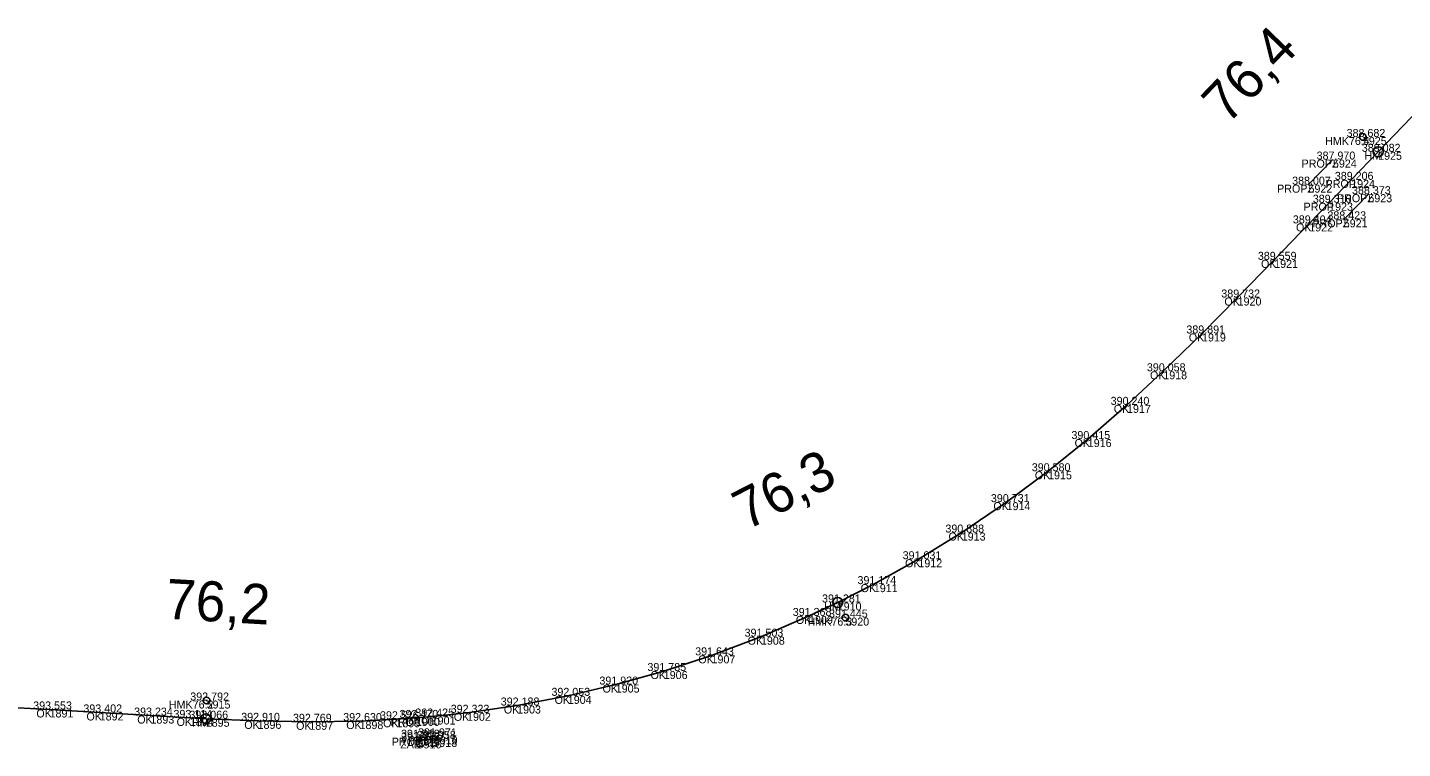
# Model space of a CAD drawing. Extents: x -621782 to -610392, y -1141853 to -1122321.
# Drawn here: x -617837.9 to -617631.7, y -1130433.5 to -1130325.4 of the extents above; entities that cross this region are included whole.
import ezdxf

# ---------------------------------------------------------------- set-up
doc = ezdxf.new("R2010")
doc.units = 0
for name, color, linetype in [('Vrstva 1', 7, 'Continuous'), ('Vrstva 17', 7, 'Continuous'), ('Vrstva 19', 7, 'Continuous'), ('Vrstva 60', 7, 'Continuous'), ('Vrstva 61', 7, 'Continuous'), ('Vrstva 62', 7, 'Continuous'), ('Vrstva 7', 7, 'Continuous')]:
    doc.layers.add(name, color=color, linetype=linetype)

msp = doc.modelspace()

# ---------------------------------------------------------------- linework, layer by layer
at = {"layer": 'Vrstva 1'}
msp.add_lwpolyline([(-617842.32, -1130427.24), (-617834.59, -1130427.64), (-617827.07, -1130428.09), (-617819.46, -1130428.56), (-617813.56, -1130428.91), (-617811.17, -1130429.03), (-617803.4, -1130429.35), (-617795.64, -1130429.49), (-617788.11, -1130429.38), (-617782.58, -1130429.11), (-617779.66, -1130428.91), (-617777.29, -1130428.7), (-617771.99, -1130428.14), (-617764.48, -1130427.05), (-617756.88, -1130425.6), (-617749.69, -1130423.91), (-617742.49, -1130421.88), (-617735.33, -1130419.53), (-617727.92, -1130416.73), (-617720.7, -1130413.62), (-617716.41, -1130411.6), (-617710.99, -1130408.85), (-617704.31, -1130405.12), (-617697.81, -1130401.12), (-617691.08, -1130396.56), (-617684.86, -1130391.93), (-617678.91, -1130387.1), (-617673.03, -1130381.97), (-617667.59, -1130376.94), (-617661.78, -1130371.27), (-617656.44, -1130365.88), (-617650.96, -1130360.23), (-617645.71, -1130354.77), (-617642.72, -1130351.67), (-617639.41, -1130348.24), (-617635.37, -1130344.03), (-617629.19, -1130337.61)], dxfattribs=at)
at = {"layer": 'Vrstva 17'}
msp.add_line((-617779.41, -1130432.28), (-617777.03, -1130432.05), dxfattribs=at)
at = {"layer": 'Vrstva 19'}
for p, q in [((-617645.82, -1130348.96), (-617642.15, -1130345.2)), ((-617640.53, -1130354.16), (-617636.84, -1130350.39)), ((-617779.43, -1130431.88), (-617776.97, -1130431.67))]:
    msp.add_line(p, q, dxfattribs=at)
at = {"layer": 'Vrstva 60'}
for p, q in [((-617637.66, -1130341.81), (-617637.66, -1130341.81)), ((-617635.37, -1130344.03), (-617635.37, -1130344.03)), ((-617642.15, -1130345.2), (-617642.15, -1130345.2)), ((-617639.41, -1130348.24), (-617639.41, -1130348.24)), ((-617645.82, -1130348.96), (-617645.82, -1130348.96)), ((-617636.84, -1130350.39), (-617636.84, -1130350.39)), ((-617642.72, -1130351.67), (-617642.72, -1130351.67)), ((-617640.53, -1130354.16), (-617640.53, -1130354.16)), ((-617645.71, -1130354.77), (-617645.71, -1130354.77)), ((-617650.96, -1130360.23), (-617650.96, -1130360.23)), ((-617656.44, -1130365.88), (-617656.44, -1130365.88)), ((-617661.78, -1130371.27), (-617661.78, -1130371.27)), ((-617667.59, -1130376.94), (-617667.59, -1130376.94)), ((-617673.03, -1130381.97), (-617673.03, -1130381.97)), ((-617678.91, -1130387.1), (-617678.91, -1130387.1)), ((-617684.86, -1130391.93), (-617684.86, -1130391.93)), ((-617691.08, -1130396.56), (-617691.08, -1130396.56)), ((-617697.81, -1130401.12), (-617697.81, -1130401.12)), ((-617704.31, -1130405.12), (-617704.31, -1130405.12)), ((-617710.99, -1130408.85), (-617710.99, -1130408.85)), ((-617716.41, -1130411.6), (-617716.41, -1130411.6)), ((-617720.7, -1130413.62), (-617720.7, -1130413.62)), ((-617715.26, -1130413.87), (-617715.26, -1130413.87)), ((-617727.92, -1130416.73), (-617727.92, -1130416.73)), ((-617735.33, -1130419.53), (-617735.33, -1130419.53)), ((-617742.49, -1130421.88), (-617742.49, -1130421.88)), ((-617749.69, -1130423.91), (-617749.69, -1130423.91)), ((-617811.04, -1130426.3), (-617811.04, -1130426.3)), ((-617756.88, -1130425.6), (-617756.88, -1130425.6)), ((-617834.59, -1130427.64), (-617834.59, -1130427.64)), ((-617827.07, -1130428.09), (-617827.07, -1130428.09)), ((-617819.46, -1130428.56), (-617819.46, -1130428.56)), ((-617777.29, -1130428.7), (-617777.29, -1130428.7)), ((-617771.99, -1130428.14), (-617771.99, -1130428.14)), ((-617764.48, -1130427.05), (-617764.48, -1130427.05)), ((-617813.56, -1130428.91), (-617813.56, -1130428.91)), ((-617811.17, -1130429.03), (-617811.17, -1130429.03)), ((-617803.4, -1130429.35), (-617803.4, -1130429.35)), ((-617795.64, -1130429.49), (-617795.64, -1130429.49)), ((-617788.11, -1130429.38), (-617788.11, -1130429.38)), ((-617782.58, -1130429.11), (-617782.58, -1130429.11)), ((-617779.66, -1130428.91), (-617779.66, -1130428.91)), ((-617779.43, -1130431.88), (-617779.43, -1130431.88)), ((-617779.41, -1130432.28), (-617779.41, -1130432.28)), ((-617777.03, -1130432.05), (-617777.03, -1130432.05)), ((-617776.97, -1130431.67), (-617776.97, -1130431.67))]:
    msp.add_line(p, q, dxfattribs=at)
at = {"layer": 'Vrstva 7'}
for p, q in [((-617637.69, -1130341.85), (-617637.62, -1130341.78)), ((-617715.3, -1130413.89), (-617715.21, -1130413.85)), ((-617811.09, -1130426.3), (-617810.99, -1130426.3))]:
    msp.add_line(p, q, dxfattribs=at)
for centre, radius in [((-617637.66, -1130341.81), 0.5), ((-617635.37, -1130344.03), 0.75), ((-617716.41, -1130411.6), 0.75), ((-617715.26, -1130413.87), 0.5), ((-617811.04, -1130426.3), 0.5), ((-617811.17, -1130429.03), 0.75)]:
    msp.add_circle(centre, radius, dxfattribs=at)

# ---------------------------------------------------------------- texts
at = {"layer": 'Vrstva 60'}
for s, p in [('5925', (-617637.66, -1130343.01)), ('1925', (-617635.37, -1130345.23)), ('5924', (-617642.15, -1130346.4)), ('1924', (-617639.41, -1130349.44)), ('5922', (-617645.82, -1130350.16)), ('5923', (-617636.84, -1130351.59)), ('1923', (-617642.72, -1130352.87)), ('5921', (-617640.53, -1130355.36)), ('1922', (-617645.71, -1130355.97)), ('1921', (-617650.96, -1130361.43)), ('1920', (-617656.44, -1130367.08)), ('1919', (-617661.78, -1130372.47)), ('1918', (-617667.59, -1130378.14)), ('1917', (-617673.03, -1130383.17)), ('1916', (-617678.91, -1130388.3)), ('1915', (-617684.86, -1130393.13)), ('1914', (-617691.08, -1130397.76)), ('1913', (-617697.81, -1130402.32)), ('1912', (-617704.31, -1130406.32)), ('1911', (-617710.99, -1130410.05)), ('1910', (-617716.41, -1130412.8)), ('1909', (-617720.7, -1130414.82)), ('5920', (-617715.26, -1130415.07)), ('1908', (-617727.92, -1130417.93)), ('1907', (-617735.33, -1130420.73)), ('1906', (-617742.49, -1130423.08)), ('1905', (-617749.69, -1130425.11)), ('5915', (-617811.04, -1130427.5)), ('1904', (-617756.88, -1130426.8)), ('1891', (-617834.59, -1130428.84)), ('1892', (-617827.07, -1130429.29)), ('1893', (-617819.46, -1130429.76)), ('1901', (-617777.29, -1130429.9)), ('1902', (-617771.99, -1130429.34)), ('1903', (-617764.48, -1130428.25)), ('1894', (-617813.56, -1130430.11)), ('1895', (-617811.17, -1130430.23)), ('1896', (-617803.4, -1130430.55)), ('1897', (-617795.64, -1130430.69)), ('1898', (-617788.11, -1130430.58)), ('1899', (-617782.58, -1130430.31)), ('1900', (-617779.66, -1130430.11)), ('5917', (-617779.43, -1130433.08)), ('5916', (-617779.41, -1130433.48)), ('5918', (-617777.03, -1130433.25)), ('5919', (-617776.97, -1130432.87))]:
    msp.add_text(s, height=1.2, dxfattribs=at).set_placement(p)
at = {"layer": 'Vrstva 61'}
for s, p in [('388.682', (-617640.1, -1130341.81)), ('387.970', (-617644.6, -1130345.2)), ('389.082', (-617637.82, -1130344.03)), ('388.007', (-617648.27, -1130348.96)), ('389.206', (-617641.87, -1130348.24)), ('388.373', (-617639.29, -1130350.39)), ('389.310', (-617645.17, -1130351.67)), ('389.404', (-617648.16, -1130354.77)), ('388.423', (-617642.98, -1130354.16)), ('389.559', (-617653.41, -1130360.23)), ('389.732', (-617658.89, -1130365.88)), ('389.891', (-617664.13, -1130371.27)), ('390.058', (-617670.05, -1130376.94)), ('390.240', (-617675.48, -1130381.97)), ('390.415', (-617681.36, -1130387.1)), ('390.580', (-617687.31, -1130391.93)), ('390.731', (-617693.44, -1130396.56)), ('390.888', (-617700.26, -1130401.12)), ('391.031', (-617706.67, -1130405.12)), ('391.174', (-617713.44, -1130408.85)), ('391.281', (-617718.76, -1130411.6)), ('391.368', (-617723.15, -1130413.62)), ('391.445', (-617717.71, -1130413.87)), ('391.503', (-617730.37, -1130416.73)), ('391.643', (-617737.78, -1130419.53)), ('391.785', (-617744.94, -1130421.88)), ('392.053', (-617759.33, -1130425.6)), ('391.920', (-617752.14, -1130423.91)), ('393.553', (-617837.04, -1130427.64)), ('392.792', (-617813.49, -1130426.3)), ('392.188', (-617766.94, -1130427.05)), ('393.402', (-617829.52, -1130428.09)), ('393.234', (-617821.91, -1130428.56)), ('393.114', (-617816.01, -1130428.91)), ('393.066', (-617813.62, -1130429.03)), ('392.910', (-617805.85, -1130429.35)), ('392.769', (-617798.09, -1130429.49)), ('392.630', (-617790.56, -1130429.38)), ('392.526', (-617785.04, -1130429.11)), ('392.470', (-617782.11, -1130428.91)), ('392.425', (-617779.74, -1130428.7)), ('392.323', (-617774.44, -1130428.14)), ('391.918', (-617781.89, -1130431.88)), ('391.971', (-617779.33, -1130431.67)), ('392.928', (-617781.86, -1130432.28)), ('392.958', (-617779.48, -1130432.05))]:
    msp.add_text(s, height=1.2, dxfattribs=at).set_placement(p)
at = {"layer": 'Vrstva 62'}
for s, p in [('HMK76.4', (-617643.32, -1130343.01)), ('HM', (-617637.4, -1130345.23)), ('PROPZ', (-617646.85, -1130346.4)), ('PROP', (-617643.25, -1130349.44)), ('PROPZ', (-617650.52, -1130350.16)), ('PROPZ', (-617641.54, -1130351.59)), ('PROP', (-617646.55, -1130352.87)), ('PROPZ', (-617645.23, -1130355.36)), ('OK', (-617647.69, -1130355.97)), ('OK', (-617652.94, -1130361.43)), ('OK', (-617658.43, -1130367.08)), ('OK', (-617663.76, -1130372.47)), ('OK', (-617669.58, -1130378.14)), ('OK', (-617675.01, -1130383.17)), ('OK', (-617680.89, -1130388.3)), ('OK', (-617686.85, -1130393.13)), ('OK', (-617693.07, -1130397.76)), ('OK', (-617699.79, -1130402.32)), ('OK', (-617706.3, -1130406.32)), ('OK', (-617712.97, -1130410.05)), ('HM', (-617718.44, -1130412.8)), ('OK', (-617722.68, -1130414.82)), ('HMK76.3', (-617720.92, -1130415.07)), ('OK', (-617729.91, -1130417.93)), ('OK', (-617737.31, -1130420.73)), ('OK', (-617744.47, -1130423.08)), ('OK', (-617751.67, -1130425.11)), ('HMK76.2', (-617816.7, -1130427.5)), ('OK', (-617758.86, -1130426.8)), ('OK', (-617836.57, -1130428.84)), ('OK', (-617829.06, -1130429.29)), ('OK', (-617821.44, -1130429.76)), ('PROP', (-617781.12, -1130429.9)), ('OK', (-617773.97, -1130429.34)), ('OK', (-617766.47, -1130428.25)), ('OK', (-617815.54, -1130430.11)), ('HM', (-617813.21, -1130430.23)), ('OK', (-617805.39, -1130430.55)), ('OK', (-617797.62, -1130430.69)), ('OK', (-617790.1, -1130430.58)), ('OK', (-617784.57, -1130430.31)), ('PROP', (-617783.49, -1130430.11)), ('PROP', (-617783.27, -1130433.08)), ('ZAB', (-617782.01, -1130433.48)), ('PROP', (-617780.8, -1130432.87)), ('ZAB', (-617779.63, -1130433.25))]:
    msp.add_text(s, height=1.2, dxfattribs=at).set_placement(p)
at = {"layer": 'Vrstva 7'}
for s, rotation, p in [('76,4', 46.0969, (-617657.98, -1130340.08)), ('76,3', 26.9404, (-617730.1, -1130400.84)), ('76,2', 356.6853, (-617817.28, -1130414.03))]:
    msp.add_text(s, height=6, rotation=rotation, dxfattribs=at).set_placement(p)

doc.saveas('drawing.dxf')
